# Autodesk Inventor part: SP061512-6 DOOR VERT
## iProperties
Created: 2012-06
Part Number: SP061512-6 DOOR VERT
Material: Aluminum-6061
Description: CLAMP PROFILE 45X32
Document SubType Name: Modeling
Designer: Administrator
Stock Number: 20.1053 CLAMP PROFILE 45X32
Density: 2.71 g/cm^3
Mass: 3152.86 g
Surface Area: 7032.01 cm^2
Volume: 1163.42 cm^3
FINISH: CLEAR ANODIZED
Author: Administrator
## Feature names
1. Extrusion1
